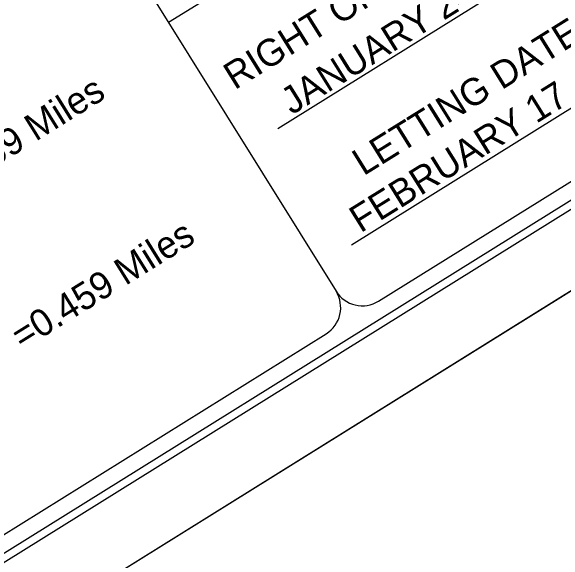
# Model space of a CAD drawing. Extents: x 2038094 to 2053858, y 751760 to 764312.
# Drawn here: x 2048875 to 2049948, y 756100 to 757168 of the extents above; entities that cross this region are included whole.
import ezdxf

# ---------------------------------------------------------------- set-up
doc = ezdxf.new("R2010")
doc.units = 0
for name, color, linetype in [('Sheet Cutting Line CELL', 7, 'Continuous'), ('Sheet Data Field CELL', 7, 'Continuous'), ('Sheet Plot Border Inside CELL', 7, 'Continuous'), ('Sheet Plot Border Outside CELL', 7, 'Continuous'), ('Sheet Title CELL', 7, 'Continuous')]:
    doc.layers.add(name, color=color, linetype=linetype)

msp = doc.modelspace()

# ---------------------------------------------------------------- linework, layer by layer
at = {"layer": 'Sheet Cutting Line CELL'}
msp.add_line((2044733.7, 753368.3), (2053310, 758710.3), dxfattribs=at)
at = {"layer": 'Sheet Plot Border Inside CELL'}
msp.add_lwpolyline([(2044728.7, 753523.8), (2053215.9, 758810.3), (2049868.9, 764183.7), (2041381.7, 758897.2)], close=True, dxfattribs=at)
at = {"layer": 'Sheet Plot Border Outside CELL'}
msp.add_lwpolyline([(2049820.6, 764312.3), (2041244.2, 758970.3), (2044733.7, 753368.3), (2053310, 758710.3)], close=True, dxfattribs=at)
at = {"layer": 'Sheet Title CELL'}
for p, q in [((2049850.9, 757562.9), (2049180.9, 757145.7)), ((2048998.5, 757438.5), (2049506.1, 756623.7)), ((2049972.1, 757300.2), (2049392.8, 756939.4)), ((2049682.4, 757119.7), (2049682.4, 757119.7)), ((2050115.6, 757074.4), (2049536.3, 756713.5))]:
    msp.add_line(p, q, dxfattribs=at)
for points in [[(2045555.8, 754057), (2053093.2, 758751.9)], [(2049588.7, 756604.4), (2051040.2, 757508.5)], [(2047551.6, 755335.5), (2049486.9, 756540.9)]]:
    msp.add_lwpolyline(points, dxfattribs=at)
for centre, start, end in [((2049455, 756592.2), 301.918, 31.918), ((2049556.9, 756655.6), 211.918, 301.918)]:
    msp.add_arc(centre, 60, start, end, dxfattribs=at)

# ---------------------------------------------------------------- texts
at = {"layer": 'Sheet Data Field CELL'}
for s, p in [('JANUARY 24, 2022', (2049420.1, 756965.4)), ('FEBRUARY 17, 2026', (2049553.6, 756736.2))]:
    msp.add_text(s, height=52.501, rotation=31.918, dxfattribs=at).set_placement(p)
at = {"layer": 'Sheet Title CELL'}
for s, height, p in [('RIGHT OF WAY DATE: ', 52.499, (2049309.3, 757013.9)), ('LETTING DATE:', 52.499, (2049559.3, 756846.9)), ('=0.459 Miles', 52.501, (2048722.2, 756789)), ('=0.459 Miles', 52.501, (2048896.5, 756509))]:
    msp.add_text(s, height=height, rotation=31.918, dxfattribs=at).set_placement(p)

doc.saveas('drawing.dxf')
